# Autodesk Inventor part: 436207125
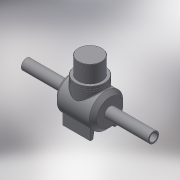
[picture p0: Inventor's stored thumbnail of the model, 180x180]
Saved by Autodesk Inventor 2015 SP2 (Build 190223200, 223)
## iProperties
Created: 2017-08
Part Number: 436207125
Material: Generic
Description: PLASSON PE BALL VALVE 125
Document SubType Name: Modeling
Designer: Кирилл
Density: 1 g/cm^3
Appearance: Default
Author: Кирилл
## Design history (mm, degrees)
derived "436207.ipt"
feature "Solid1::436207.ipt"
feature "Solid2::436207.ipt"
tag "TaggingFeature1"
body "Solid1"
other parameters: "d1" = 125, "d3" = 182, "d5" = 81.25, "d6" = 16.5, "d10" = 85, "d11" = 68, "d12" = 0.85, "d13" = 4, "d14" = 4, "d16" = 100 deg, "d18" = 16, "d20" = 93, "d21" = 0, "d22" = 0.85, "d26" = 12, "d28" = 0, "d29" = 1.7, "d_" = 125, "s_" = 12, "L_1" = 182, "B_" = 93, "E_1" = 85
